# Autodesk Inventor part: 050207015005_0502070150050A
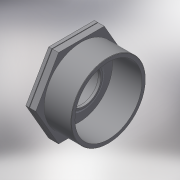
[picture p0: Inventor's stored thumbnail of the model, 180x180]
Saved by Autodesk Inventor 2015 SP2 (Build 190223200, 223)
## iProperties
Created: 2017-05
Part Number: 050207015005_0502070150050A
Material: Generic
Description: PLASSON REDUCING BUSHING 1.1/2"-1/2"
Document SubType Name: Modeling
Designer: KIM
Density: 1 g/cm^3
Appearance: Default
Author: KIM
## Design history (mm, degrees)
derived "050207.ipt"
feature "Solid1::050207.ipt"
tag "TaggingFeature1"
body "Solid1"
other parameters: "d1" = 47.803, "d5" = 21, "d8" = 0.37, "d12" = 0, "d15" = 37, "d19" = 0, "d30" = 9.25, "d31" = 4.625, "d33" = 18.631, "d34" = 43.0227, "d36" = 2.5, "d37" = 22.3572, "d38" = 24.42, "d39" = 16.7679, "d40" = 2.1, "d41" = 0, "H_" = 37, "R_" = 47.803, "l_2" = 21, "Rp_" = 18.631
